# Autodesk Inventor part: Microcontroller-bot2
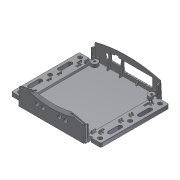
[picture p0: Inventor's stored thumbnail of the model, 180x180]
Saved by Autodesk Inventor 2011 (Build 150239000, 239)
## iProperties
Created: 2010-06
Part Number: Microcontroller-bot2
Document SubType Name: Modeling
Designer: kurdi
Density: 1 g/cm^3
Author: kurdi
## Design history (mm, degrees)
sketch "Sketch2"
  geometry: L1 (47.625, 12.7)-(47.625, 25.4); L2 (48.625, 12.7)-(48.625, 25.4); L3 (52.975, 25.4)-(52.975, 12.7); L4 (55.15, 1.25)-(55.15, 41.5); L5 (46.825, 42)-(54.65, 42); L6 (46.325, 40.5)-(46.325, 41.5); L7 (41.65, 40)-(45.825, 40); L8 (41.15, 34)-(41.15, 39.5); L9 (46.15, 24)-(46.15, 33); L10 (41.65, 33.5)-(45.65, 33.5); L11 (45.65, 23.5)-(41.65, 23.5); L12 (41.15, 0.5)-(41.15, 23); L13 (47.665, 0.5)-(41.15, 0.5); L14 (54.65, 0.75)-(54.256, 0.75); L15 (55.145, 43.511)-(44.825, 43.511); L16 (0, 0)-(91.681, 0) reference; L17 (0, 0)-(0, 55.36) reference; L18 (44.825, 43.511)-(44.825, 41.717); L19 (53.975, 25.4)-(53.975, 12.7); L20 (44.825, 41.717)-(42.375, 41.717); L21 (42.375, 41.717)-(42.375, 43.773); L22 (42.375, 43.773)-(42.7, 43.773); L23 (42.7, 43.773)-(42.7, 45.36); L24 (42.375, 45.36)-(42.7, 45.36); L25 (42.375, 45.36)-(42.375, 48.457); L26 (42.375, 48.457)-(41.363, 48.457); L27 (41.363, 48.457)-(41.363, 49.282); L28 (-41.15, 34)-(-41.15, 39.5); L29 (-46.325, 40.5)-(-46.325, 41.5); L30 (-46.825, 42)-(-54.65, 42); L31 (-46.15, 24)-(-46.15, 33); L32 (-47.625, 12.7)-(-47.625, 25.4); L33 (-48.625, 12.7)-(-48.625, 25.4); L34 (-45.65, 23.5)-(-41.65, 23.5); L35 (-55.15, 1.25)-(-55.15, 41.5); L36 (-52.975, 25.4)-(-52.975, 12.7); L37 (-41.15, 0.5)-(-41.15, 23); L38 (-41.65, 33.5)-(-45.65, 33.5); L39 (-41.65, 40)-(-45.825, 40); L40 (-55.145, 43.511)-(-44.825, 43.511); L41 (-47.665, 0.5)-(-41.15, 0.5); L42 (-54.65, 0.75)-(-54.256, 0.75); L43 (-44.825, 41.717)-(-42.375, 41.717); L44 (-44.825, 43.511)-(-44.825, 41.717); L45 (-42.375, 41.717)-(-42.375, 43.773); L46 (-42.375, 43.773)-(-42.7, 43.773); L47 (-42.7, 43.773)-(-42.7, 45.36); L48 (-42.375, 45.36)-(-42.375, 48.457); L49 (-42.375, 48.457)-(-41.363, 48.457); L50 (-41.363, 48.457)-(-41.363, 49.282); L51 (-42.375, 45.36)-(-42.7, 45.36); L52 (-53.975, 25.4)-(-53.975, 12.7); L53 (55.15, -1.25)-(55.15, -41.5); L54 (41.15, -0.5)-(41.15, -23); L55 (41.15, -34)-(41.15, -39.5); L56 (41.65, -40)-(45.825, -40); L57 (46.325, -40.5)-(46.325, -41.5); L58 (0, 0)-(0, -55.36); L59 (41.363, -48.457)-(41.363, -49.282); L60 (42.375, -48.457)-(41.363, -48.457); L61 (42.375, -41.717)-(42.375, -43.773); L62 (42.375, -45.36)-(42.7, -45.36); L63 (42.7, -43.773)-(42.7, -45.36); L64 (42.375, -43.773)-(42.7, -43.773)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; C1 r 2.175 at (50.8, 0); C2 r 2.75 at (36.195, 41.91); C3 r 1.4 at (36.195, 41.91); C4 r 3.25 at (50.8, 38.1); C5 r 2.175 at (50.8, 38.1); C6 r 2.175 at (-50.8, 38.1); C7 r 3.25 at (-50.8, 38.1); C8 r 2.175 at (-50.8, 0); C9 r 2.75 at (-36.195, 41.91); C10 r 1.4 at (-36.195, 41.91); C11 r 2.75 at (36.195, -41.91); C12 r 1.4 at (36.195, -41.91); C13 r 1.4 at (-36.195, -41.91); C14 r 2.75 at (-36.195, -41.91); C15 r 2.175 at (-50.8, -38.1); C16 r 3.25 at (-50.8, -38.1); C17 r 3.25 at (50.8, -38.1); C18 r 2.175 at (50.8, -38.1); A1 r 2.95 centre (50.8, 38.1) between (53.193, 39.825) and (48.592, 40.057); A2 r 2.175 centre (50.8, 25.4) between (52.975, 25.4) and (48.625, 25.4); A3 r 2.175 centre (50.8, 12.7) between (48.625, 12.7) and (52.975, 12.7); A4 r 0.5 centre (54.65, 41.5) between (55.15, 41.5) and (54.65, 42); A5 r 0.5 centre (46.825, 41.5) between (46.825, 42) and (46.325, 41.5); A6 r 0.5 centre (45.825, 40.5) between (45.825, 40) and (46.325, 40.5); A7 r 0.5 centre (41.65, 39.5) between (41.65, 40) and (41.15, 39.5); A8 r 0.5 centre (41.65, 34) between (41.15, 34) and (41.65, 33.5); A9 r 0.5 centre (45.65, 33) between (46.15, 33) and (45.65, 33.5); A10 r 0.5 centre (45.65, 24) between (45.65, 23.5) and (46.15, 24); A11 r 0.5 centre (41.65, 23) between (41.65, 23.5) and (41.15, 23); A12 r 3.175 centre (50.8, 0) between (53.786, 1.08) and (47.665, 0.5); A13 r 0.5 centre (54.256, 1.25) between (53.786, 1.08) and (54.256, 0.75); A14 r 0.5 centre (54.65, 1.25) between (54.65, 0.75) and (55.15, 1.25); A15 r 3.175 centre (50.8, 12.7) between (47.625, 12.7) and (53.975, 12.7); A16 r 3.175 centre (50.8, 25.4) between (53.975, 25.4) and (47.625, 25.4); A17 r 0.5 centre (-45.825, 40.5) between (-46.325, 40.5) and (-45.825, 40); A18 r 0.5 centre (-46.825, 41.5) between (-46.325, 41.5) and (-46.825, 42); A19 r 2.95 centre (-50.8, 38.1) between (-48.592, 40.057) and (-53.193, 39.825); A20 r 0.5 centre (-54.65, 41.5) between (-54.65, 42) and (-55.15, 41.5); A21 r 2.175 centre (-50.8, 25.4) between (-48.625, 25.4) and (-52.975, 25.4); A22 r 0.5 centre (-45.65, 33) between (-45.65, 33.5) and (-46.15, 33); A23 r 2.175 centre (-50.8, 12.7) between (-52.975, 12.7) and (-48.625, 12.7); A24 r 0.5 centre (-45.65, 24) between (-46.15, 24) and (-45.65, 23.5); A25 r 0.5 centre (-41.65, 23) between (-41.15, 23) and (-41.65, 23.5); A26 r 3.175 centre (-50.8, 0) between (-47.665, 0.5) and (-53.786, 1.08); A27 r 0.5 centre (-41.65, 34) between (-41.65, 33.5) and (-41.15, 34); A28 r 0.5 centre (-41.65, 39.5) between (-41.15, 39.5) and (-41.65, 40); A29 r 0.5 centre (-54.256, 1.25) between (-54.256, 0.75) and (-53.786, 1.08); A30 r 0.5 centre (-54.65, 1.25) between (-55.15, 1.25) and (-54.65, 0.75); A31 r 3.175 centre (-50.8, 25.4) between (-47.625, 25.4) and (-53.975, 25.4); A32 r 3.175 centre (-50.8, 12.7) between (-53.975, 12.7) and (-47.625, 12.7); A33 r 0.5 centre (45.825, -40.5) between (46.325, -40.5) and (45.825, -40); A34 r 0.5 centre (41.65, -39.5) between (41.15, -39.5) and (41.65, -40); A35 r 0.5 centre (41.65, -34) between (41.65, -33.5) and (41.15, -34); A36 r 0.5 centre (41.65, -23) between (41.15, -23) and (41.65, -23.5); A37 r 0.5 centre (45.65, -24) between (46.15, -24) and (45.65, -23.5); A38 r 0.5 centre (45.65, -33) between (45.65, -33.5) and (46.15, -33); A39 r 0.5 centre (54.256, -1.25) between (54.256, -0.75) and (53.786, -1.08); A40 r 3.175 centre (50.8, 0) between (47.665, -0.5) and (53.786, -1.08); A41 r 0.5 centre (54.65, -1.25) between (55.15, -1.25) and (54.65, -0.75); A42 r 0.5 centre (54.65, -41.5) between (54.65, -42) and (55.15, -41.5); A43 r 0.5 centre (46.825, -41.5) between (46.325, -41.5) and (46.825, -42); A44 r 0.5 centre (-45.825, -40.5) between (-45.825, -40) and (-46.325, -40.5); A45 r 2.95 centre (-50.8, -38.1) between (-53.193, -39.825) and (-48.592, -40.057); A46 r 0.5 centre (-45.65, -33) between (-46.15, -33) and (-45.65, -33.5); A47 r 0.5 centre (-41.65, -34) between (-41.15, -34) and (-41.65, -33.5); A48 r 3.175 centre (-50.8, -25.4) between (-53.975, -25.4) and (-47.625, -25.4); A49 r 2.175 centre (-50.8, -25.4) between (-52.975, -25.4) and (-48.625, -25.4); A50 r 0.5 centre (-45.65, -24) between (-45.65, -23.5) and (-46.15, -24); A51 r 0.5 centre (-41.65, -23) between (-41.65, -23.5) and (-41.15, -23); A52 r 2.175 centre (-50.8, -12.7) between (-48.625, -12.7) and (-52.975, -12.7); A53 r 3.175 centre (-50.8, 0) between (-53.786, -1.08) and (-47.665, -0.5); A54 r 0.5 centre (-54.65, -1.25) between (-54.65, -0.75) and (-55.15, -1.25); A55 r 3.175 centre (-50.8, -12.7) between (-47.625, -12.7) and (-53.975, -12.7); A56 r 0.5 centre (-46.825, -41.5) between (-46.825, -42) and (-46.325, -41.5); A57 r 0.5 centre (-54.65, -41.5) between (-55.15, -41.5) and (-54.65, -42); A58 r 0.5 centre (-41.65, -39.5) between (-41.65, -40) and (-41.15, -39.5); A59 r 0.5 centre (-54.256, -1.25) between (-53.786, -1.08) and (-54.256, -0.75); A60 r 2.175 centre (50.8, -12.7) between (52.975, -12.7) and (48.625, -12.7); A61 r 3.175 centre (50.8, -12.7) between (53.975, -12.7) and (47.625, -12.7); A62 r 3.175 centre (50.8, -25.4) between (47.625, -25.4) and (53.975, -25.4); A63 r 2.175 centre (50.8, -25.4) between (48.625, -25.4) and (52.975, -25.4); 17 further points
  constraints: 234 end point, 194 symmetric about line, 126 point on circle, 81 centre point, 20 perpendicular, 8 coincident, 4 tangent, 3 point on line, 2 collinear, 1 parallel, 91 other
  dimensions: "d9" = 99.16393 distance between parallel lines of L100 L102; "d10" = 114.28925 distance between parallel lines of L103 L101
extrude "Extrusion1" new body sketch "Sketch2" distance "d2" = 5.0038; taper "d3" = -1 deg
feature "FaceDraft6" dims angle "d95" = 1 deg
extrude "Extrusion2" cut sketch "Sketch2" distance "d4" = 2.9972; taper "d5" = 0 deg
fillet "Fillet1" dims "d6" = 0.3048
fillet "Fillet2" dims "d7" = 0.3048
fillet "Fillet3" dims "d8" = 0.3048
sketch "Sketch3"
  geometry: L1 (-48.238, 12.7)-(-48.238, 25.4) reference; L2 (-39.141, -39.073)-(-39.141, 39.073); L3 (-40.183, -47.498)-(40.183, -47.498); L4 (40.183, 47.498)-(-40.183, 47.498); L5 (-40.183, 47.498)-(-40.183, 43.356); L6 (-40.183, -43.356)-(-40.183, -47.498); L7 (39.141, -38.859)-(39.141, 38.858); L8 (40.183, -47.498)-(40.183, -43.356); L9 (40.183, 43.356)-(40.183, 47.498); C1 r 2.837 at (-36.195, -41.91) reference; C2 r 2.837 at (36.195, -41.91) reference; C3 r 2.837 at (-36.195, 41.91) reference; C4 r 2.837 at (36.195, 41.91) reference; A1 r 4.242 centre (-36.195, -41.91) between (-40.183, -43.356) and (-39.141, -38.858); A2 r 4.242 centre (-36.195, 41.91) between (-39.141, 38.858) and (-40.183, 43.356); A3 r 4.242 centre (36.195, -41.91) between (39.141, -38.859) and (40.183, -43.356); A4 r 4.242 centre (36.195, 41.91) between (40.183, 43.356) and (39.141, 38.858); 1 further point
  constraints: 16 end point, 8 point on circle, 7 parallel, 4 centre point, 4 coincident, 3 equal radius, 2 collinear, 2 perpendicular, 2 point on line, 1 horizontal
  dimensions: "d11" = 47.498 distance from line of L3 point (0, 0); "d12" = 47.498 distance from line of L4 point (0, 0); "d13" = 8.4836 diameter of A1; "d15" = 39.1414 distance from line of L2 point (0, 0); "d16" = 40.1828 distance from line of point (0, 0) L6; "d17" = 39.1414 distance from line of point (0, 0) L7; "d18" = 40.1828 distance from line of L8 point (0, 0)
extrude "Extrusion3" cut sketch "Sketch3" distance "d19" = 2.9972; taper "d20" = 0 deg
sketch "Sketch4"
  geometry: L1 (-40.208, 38.989)-(-41.504, 38.989); L2 (-41.504, 38.989)-(-41.504, 33.985); L3 (-41.504, 33.985)-(-40.208, 33.985); L4 (-40.208, 33.985)-(-40.208, 38.989); L5 (-44.171, 25.502)-(-41.859, 25.502); L6 (-41.859, 25.502)-(-41.859, 31.496); L7 (-41.859, 31.496)-(-44.171, 31.496); L8 (-44.171, 31.496)-(-44.171, 25.502); L9 (-44.45, 34.011)-(-47.447, 34.011); L10 (-47.447, 34.011)-(-47.447, 33.02); L11 (-47.447, 33.02)-(-44.45, 33.02); L12 (-44.45, 33.02)-(-44.45, 34.011); L13 (-44.45, 31.013)-(-47.447, 31.013); L14 (-47.447, 31.013)-(-47.447, 30.023); L15 (-47.447, 30.023)-(-44.45, 30.023); L16 (-44.45, 30.023)-(-44.45, 31.013); C1 r 2.837 at (-36.195, 41.91) reference; A1 r 4.242 centre (-36.195, 41.91) between (-39.141, 38.858) and (-40.183, 43.356) reference; 1 further point
  constraints: 32 end point, 8 parallel, 4 horizontal, 4 perpendicular, 3 collinear
  dimensions: "d21" = 1.2954 distance of L1.start L1.end; "d22" = 5.0038 distance of L1.end L2.end; "d23" = 4.0132 distance from line of A1.centre L4; "d24" = 2.921 distance from line of A1.centre L1; "d25" = 5.6642 distance from line of A1.centre L6; "d26" = 10.414 distance from line of C1.centre L7; "d27" = 5.9944 distance of L7.end L5.start; "d28" = 2.3114 distance of L5.start L5.end; "d29" = 0.9906 distance of L9.end L10.end; "d30" = 2.9972 distance of L9.start L9.end; "d31" = 8.255 distance from line of A1.centre L12; "d32" = 7.8994 distance from line of C1.centre L9; "d33" = 2.0066 distance between parallel lines of L13 L11
extrude "Extrusion4" join sketch "Sketch4" distance "d34" = 3.6068; taper "d35" = -2 deg
extrude "Extrusion5" cut sketch "Sketch4" distance "d36" = 3.5052; taper "d37" = 0 deg
extrude "Extrusion6" join sketch "Sketch4" distance "d38" = 2.4892; taper "d39" = 0 deg
chamfer "Chamfer1" distance "d40" = 2.4892; stored, may be unused: second distance "d41" = 3.175, angle "d42" = 45 deg
workplane "Work Plane1"
mirror "Mirror1"
mirror "Mirror2"
mirror "Mirror3"
mirror "Mirror4"
sketch "Sketch5"
  geometry: L1 (-40.183, 43.356)-(-40.183, 47.498) reference; L2 (-39.141, 38.858)-(-39.141, 44.962); L3 (-39.141, -38.858)-(-39.141, 38.858) reference; L4 (39.141, 38.858)-(39.141, -38.859) reference; L5 (-48.238, 12.7)-(-48.238, 25.4) reference; L6 (-39.141, -38.858)-(-39.141, -44.961); L7 (39.141, -38.859)-(39.141, -44.962); L8 (39.141, 38.858)-(39.141, 44.961); C1 r 2.837 at (-36.195, 41.91) reference; C2 r 1.397 at (-36.195, 41.91); C3 r 2.837 at (-36.195, -41.91) reference; C4 r 2.837 at (36.195, 41.91) reference; C5 r 1.397 at (-36.195, -41.91); C6 r 1.397 at (36.195, -41.91); C7 r 1.397 at (36.195, 41.91); A1 r 4.242 centre (-36.195, 41.91) between (-39.141, 38.858) and (-40.183, 43.356) reference; A2 r 4.242 centre (-36.195, 41.91) between (-39.141, 38.858) and (-39.141, 44.962); A3 r 4.242 centre (-36.195, -41.91) between (-40.183, -43.356) and (-39.141, -38.858) reference; A4 r 4.242 centre (36.195, 41.91) between (40.183, 43.356) and (39.141, 38.858) reference; A5 r 4.242 centre (36.195, -41.91) between (39.141, -38.859) and (40.183, -43.356) reference; A6 r 4.242 centre (-36.195, -41.91) between (-39.141, -44.961) and (-39.141, -38.858); A7 r 4.242 centre (36.195, -41.91) between (39.141, -38.859) and (39.141, -44.962); A8 r 4.242 centre (36.195, 41.91) between (39.141, 44.961) and (39.141, 38.858); 1 further point
  constraints: 12 point on circle, 8 centre point, 8 end point, 7 coincident, 4 equal radius, 3 collinear, 2 parallel, 1 concentric
  dimensions: "d44" = 2.794 diameter of C2
extrude "Extrusion7" join sketch "Sketch5" distance "d45" = 0.9906; taper "d46" = 0 deg
sketch "Sketch6"
  geometry: C1 r 1.397 at (0, 0) reference; C2 r 2.837 at (0, 0) reference; C3 r 1.397 at (0, 83.82) reference; C4 r 2.837 at (0, 83.82) reference; C5 r 1.397 at (72.39, 0) reference; C6 r 2.837 at (72.39, 0) reference; C7 r 1.397 at (72.39, 83.82) reference; C8 r 2.837 at (72.39, 83.82) reference; 1 further point
extrude "Extrusion8" join sketch "Sketch6" distance "d47" = 1.2192; taper "d48" = 0 deg
feature "FaceDraft1" dims angle "d49" = 1 deg
feature "FaceDraft2" dims angle "d50" = -1 deg
sketch "Sketch7"
  geometry: L1 (82.814, 0)-(0, 0) reference; L2 (82.814, 0)-(-0.001, 0); L3 (41.363, 0.865)-(41.422, 25.357); L4 (82.814, 0)-(82.183, 19.389); L5 (-0.001, 0)-(0.711, 19.069); C1 r 1.6 at (23.363, 13.636); C2 r 1.6 at (31.063, 13.636); C3 r 1.6 at (51.663, 13.636); C4 r 1.6 at (59.363, 13.636); A1 r 156.845 centre (42.062, -131.487) between (81.422, 20.339) and (1.463, 20.013); A2 r 1.016 centre (1.726, 19.031) between (1.463, 20.013) and (0.711, 19.069); A3 r 1.016 centre (81.167, 19.356) between (82.183, 19.389) and (81.422, 20.339); 2 further points
  constraints: 8 end point, 8 point on circle, 7 centre point, 4 tangent, 3 horizontal alignment, 2 collinear, 1 equal radius
  dimensions: "d53" = 156.845 radius of A1; "d55" = 132.35208 vertical distance of L3.start A1.centre; "d56" = 1.016 radius of A2; "d58" = 18.00015 horizontal distance of L3.start C1.centre; "d59" = 17.99985 horizontal distance of L3.start C4.centre; "d60" = 10.29985 horizontal distance of L3.start C3.centre; "d61" = 10.30015 horizontal distance of L3.start C2.centre; "d62" = 12.77056 vertical distance of L3.start C1.centre; "d63" = 3.2004 diameter of C1; "d64" = 3.2004 diameter of C2; "d65" = 3.2004 diameter of C3; "d66" = 3.2004 diameter of C4; "d96" = 2 deg angle of L3 L4; "d97" = 2 deg angle of L3 L5
extrude "Extrusion9" join sketch "Sketch7" stored distance "d75" = 1.2192; taper "d76" = 0 deg
sketch "Sketch8"
  geometry: L1 (0, 0)-(0.262, 5.005) reference; L2 (84.837, 0)-(84.662, 5.005) reference; L3 (-0.001, -0.02)-(1.128, 21.534); L4 (84.838, -0.02)-(84.101, 21.072); L5 (-0.001, -0.02)-(84.838, -0.02); L6 (42.419, -0.02)-(42.419, 26.836); A1 r 156.845 centre (41.763, -131.506) between (82.362, 19.993) and (2.403, 20.32) reference; A2 r 158.344 centre (41.763, -131.506) between (84.101, 21.072) and (1.128, 21.534); 8 further points; 2 other entities
  constraints: 8 end point, 4 collinear, 3 point on circle, 2 horizontal, 1 centre point, 1 concentric, 1 vertical, 3 other
  dimensions: "d77" = 1.4986 radial gap between concentric circles of A1 A2
extrude "Extrusion10" join sketch "Sketch8" stored distance "d79" = 0.889; taper "d80" = 0 deg
sketch "Sketch9"
  geometry: C1 r 1.6 at (0, 0) reference; C2 r 1.6 at (7.7, 0) reference; C3 r 1.6 at (28.3, 0) reference; C4 r 1.6 at (36, 0) reference; 1 further point
  node "Projected Loop4"
  node "Projected Loop5"
  node "Projected Loop6"
extrude "Extrusion19" cut sketch "Sketch9" stored distance "d133" = 12.7; taper "d134" = 0 deg
fillet "Fillet4" dims "d85" = 1.016
chamfer "Chamfer2" distance "d86" = 0.762; stored, may be unused: second distance "d87" = 3.175, angle "d88" = 45 deg
sketch "Sketch10"
  geometry: L1 (42.613, -45.273)-(42.2, -45.273) reference; L2 (42.613, -43.86)-(42.613, -45.273) reference; L3 (42.287, -43.86)-(42.613, -43.86) reference; L4 (40.183, -43.406)-(40.183, -47.498) reference; L5 (44.171, -31.496)-(41.859, -31.496) reference; L6 (41.413, -47.559)-(41.413, -45.273); L7 (41.413, -43.86)-(41.413, -42.87); L8 (41.413, -42.87)-(40.183, -42.87); L9 (40.183, -42.87)-(40.183, -43.406); L10 (41.413, -45.273)-(42.2, -45.273); L11 (41.413, -43.86)-(42.287, -43.86); L12 (41.413, -47.559)-(40.183, -47.559); L13 (40.183, -47.559)-(40.183, -47.498); L14 (41.413, -43.86)-(40.183, -43.86); L15 (40.183, -43.86)-(40.183, -43.406); L16 (40.183, -43.86)-(40.183, -47.498); L17 (-41.177, -49.495)-(-41.176, -48.37) reference; L18 (41.413, -43.86)-(41.412, -44.114); L19 (41.412, -44.114)-(40.183, -44.114); 1 further point
  constraints: 26 end point, 5 perpendicular, 4 collinear, 3 parallel, 2 point on line, 1 horizontal, 1 vertical
  dimensions: "d89" = 0.7874 distance of L6.end L1.end; "d90" = 2.286 distance between parallel lines of L10 L12; "d91" = 0.9906 distance between parallel lines of L11 L8; "d262" = 0.254 distance of L7.start L18.end
extrude "Extrusion12" join sketch "Sketch10" distance "d92" = 12.8524; taper "d93" = 0 deg
feature "FaceDraft7" dims angle "d98" = 1 deg
chamfer "Chamfer9" distance "d247" = 12.7; stored, may be unused: second distance "d248" = 0.2032, angle "d249" = 45 deg
chamfer "Chamfer10" distance "d250" = 12.7; stored, may be unused: second distance "d251" = 0.2032, angle "d252" = 45 deg
feature "FaceDraft15" dims angle "d272" = 2 deg
sketch "Sketch13"
  geometry: L1 (40.183, -44.288)-(42.164, -44.288) reference; L2 (40.183, -47.498)-(40.183, -44.288) reference; L3 (41.413, -47.498)-(40.183, -47.498) reference; L4 (41.413, -45.07)-(41.413, -47.498) reference; L5 (42.164, -45.07)-(41.413, -45.07) reference; L6 (42.164, -44.288)-(42.164, -45.07) reference; 1 further point
extrude "Extrusion13" join sketch "Sketch13" distance "d101" = 1.524; taper "d102" = 0 deg
fillet "Fillet5" dims "d103" = 1.016
extrude "Extrusion17" join sketch "Sketch10" distance "d125" = 5.9944; taper "d126" = 0 deg
chamfer "Chamfer3" distance "d127" = 5.0038; stored, may be unused: second distance "d128" = 0.508, angle "d129" = 45 deg
mirror "Mirror5"
feature "FaceDraft9" dims angle "d100" = 2 deg
sketch "Sketch23"
  geometry: L1 (-1.981, 3.434)-(-1.981, 2.428) reference; L2 (-0.781, 2.428)-(-1.981, 2.428) reference; L3 (-0.781, 0)-(-0.781, 2.428) reference; L4 (0, 0)-(-0.781, 0) reference; L5 (0, 0)-(0, 3.434) reference; L6 (-1.981, 3.434)-(0, 3.434) reference; 1 further point
extrude "Extrusion27" join sketch "Sketch23" distance "d259" = 1.524; taper "d260" = 0 deg
fillet "Fillet6" dims "d261" = 1.016
sketch "Sketch14"
  geometry: L1 (82.816, 0.099)-(0.002, -0.099); L2 (82.816, 0.099)-(0.001, -0.099); L3 (41.363, 0.867)-(41.363, 25.357); L4 (82.816, 0.099)-(82.139, 19.486); L5 (0.001, -0.099)-(0.667, 18.972); L6 (48.817, 10.871)-(62.341, 10.871); L7 (47.928, 19.083)-(47.928, 11.76); L8 (52.378, 19.972)-(48.817, 19.972); L9 (52.378, 21.672)-(52.378, 19.972); L10 (58.782, 21.672)-(52.378, 21.672); L11 (58.782, 19.972)-(58.782, 21.672); L12 (62.341, 19.972)-(58.782, 19.972); L13 (63.23, 11.76)-(63.23, 19.083); L14 (64.968, 15.186)-(64.968, 12.685); L15 (70.268, 12.685)-(70.268, 15.186); L16 (30.867, 6.782)-(30.867, 6.97); L17 (27.818, 6.782)-(30.867, 6.782); L18 (27.818, 6.782)-(27.818, 6.97); L19 (18.667, 6.97)-(27.818, 6.97); L20 (18.667, 6.782)-(18.667, 6.97); L21 (14.618, 6.782)-(18.667, 6.782); L22 (14.618, 6.782)-(14.618, 6.97); L23 (10.208, 6.97)-(14.618, 6.97); L24 (9.318, 19.083)-(9.319, 7.859); L25 (46.429, 19.972)-(10.207, 19.972); L26 (47.319, 7.859)-(47.318, 19.083); L27 (42.567, 6.97)-(46.43, 6.97); L28 (42.567, 6.782)-(42.567, 6.97); L29 (39.518, 6.782)-(42.567, 6.782); L30 (39.518, 6.782)-(39.518, 6.97); L31 (30.867, 6.97)-(39.518, 6.97); L32 (65.349, 15.184)-(65.349, 12.684); L33 (69.887, 12.674)-(69.887, 15.184); L34 (46.937, 19.083)-(46.938, 7.859); L35 (46.429, 7.351)-(42.567, 7.351); L36 (39.518, 7.351)-(30.867, 7.351); L37 (27.818, 7.351)-(18.667, 7.351); L38 (14.618, 7.351)-(10.207, 7.351); L39 (9.7, 7.859)-(9.699, 19.083); L40 (10.207, 19.591)-(46.429, 19.591); L41 (62.849, 19.083)-(62.849, 11.76); L42 (62.341, 11.252)-(48.817, 11.252); L43 (48.309, 11.76)-(48.309, 19.083); L44 (48.817, 19.591)-(52.759, 19.591); L45 (52.759, 19.591)-(52.759, 21.291); L46 (52.759, 21.291)-(58.401, 21.291); L47 (58.401, 21.291)-(58.401, 19.591); L48 (58.401, 19.591)-(62.341, 19.591); L49 (42.567, 7.351)-(42.567, 6.782); L50 (42.567, 6.782)-(39.518, 6.782); L51 (39.518, 7.351)-(39.518, 6.782); L52 (30.867, 7.351)-(30.867, 6.782); L53 (30.867, 6.782)-(27.818, 6.782); L54 (27.818, 6.782)-(27.818, 7.351); L55 (14.618, 7.351)-(14.618, 6.782); L56 (14.618, 6.782)-(18.667, 6.782); L57 (18.667, 6.782)-(18.667, 7.351); L58 (1.18, 2.043)-(81.546, 2.043) reference; L59 (30.867, 7.351)-(26, 7.351); A1 r 156.845 centre (42.378, -131.485) between (81.376, 20.435) and (1.417, 19.917); A2 r 1.016 centre (1.683, 18.937) between (1.417, 19.917) and (0.667, 18.972); A3 r 1.016 centre (81.123, 19.451) between (82.139, 19.486) and (81.376, 20.435); A4 r 0.889 centre (48.817, 19.083) between (48.817, 19.972) and (47.928, 19.083); A5 r 0.889 centre (62.341, 19.083) between (63.23, 19.083) and (62.341, 19.972); A6 r 0.889 centre (48.817, 11.76) between (47.928, 11.76) and (48.817, 10.871); A7 r 0.889 centre (62.341, 11.76) between (62.341, 10.871) and (63.23, 11.76); A8 r 0.889 centre (46.43, 7.859) between (46.43, 6.97) and (47.319, 7.859); A9 r 0.889 centre (46.429, 19.083) between (47.318, 19.083) and (46.429, 19.972); A10 r 0.889 centre (10.207, 19.083) between (10.207, 19.972) and (9.318, 19.083); A11 r 0.889 centre (10.208, 7.859) between (9.319, 7.859) and (10.208, 6.97); A12 r 0.508 centre (46.43, 7.859) between (46.429, 7.351) and (46.938, 7.859); A13 r 0.508 centre (10.208, 7.859) between (9.7, 7.859) and (10.207, 7.351); A14 r 0.508 centre (10.207, 19.083) between (10.207, 19.591) and (9.699, 19.083); A15 r 0.508 centre (46.429, 19.083) between (46.937, 19.083) and (46.429, 19.591); A16 r 0.508 centre (62.341, 11.76) between (62.341, 11.252) and (62.849, 11.76); A17 r 0.508 centre (48.817, 11.76) between (48.309, 11.76) and (48.817, 11.252); A18 r 0.508 centre (48.817, 19.083) between (48.817, 19.591) and (48.309, 19.083); A19 r 0.508 centre (62.341, 19.083) between (62.849, 19.083) and (62.341, 19.591); 2 further points
  constraints: 116 end point, 40 point on circle, 20 tangent, 19 centre point, 8 point on line, 7 perpendicular, 6 collinear, 6 parallel, 5 vertical, 4 horizontal, 2 horizontal alignment, 1 equal radius, 26 other
  dimensions: "d104" = 156.845 radius of A1; "d105" = 132.35208 vertical distance of L3.start A1.centre; "d106" = 1.016 radius of A2; "d116" = 2 deg angle of L3 L4; "d117" = 2 deg angle of L3 L5; "d140" = 0.381 distance between parallel lines of L14 L32; "d141" = 0.889 radius of A4; "d142" = 0.889 radius of A5; "d143" = 0.889 radius of A6; "d144" = 0.889 radius of A7; "d145" = 0.889 radius of A8; "d146" = 0.889 radius of A9; "d147" = 0.889 radius of A10; "d148" = 0.889 radius of A11; "d149" = 0.381 distance between parallel lines of L26 L34; "d150" = 0.381 distance between parallel lines of L41 L13; "d168" = 5.3086 distance between parallel lines of L58 L59; "d169" = 0.61 distance between parallel lines of L7 L26; "d170" = 3.561 distance of L8.start L8.end; "d171" = 5.64198 distance of L45.end L46.end; "d172" = 3.94001 distance of L47.end L48.end; "d173" = 3.942 distance of L44.start L44.end; "d174" = 36.222 distance of L40.start L40.end; "d175" = 37.238 distance between parallel lines of L34 L39; "d176" = 9.15069 distance of L37.start L37.end; "d177" = 8.65069 distance of L36.start L36.end; "d178" = 4.411 distance of L38.start L38.end; "d179" = 3.86169 distance of L35.start L35.end; "d181" = 12.23986 distance between parallel lines of L37 L40; "d182" = 0.381 distance between parallel lines of L19 L37; "d183" = 0.381 distance between parallel lines of L23 L38; "d184" = 0.381 distance between parallel lines of L31 L36; "d185" = 0.381 distance between parallel lines of L27 L35; "d186" = 0.381 distance between parallel lines of L25 L40; "d187" = 3.90059 distance between parallel lines of L6 L27; "d188" = 2.50077 distance of L15.start L15.end; "d189" = 5.3 distance between parallel lines of L14 L15; "d190" = 8.33926 distance between parallel lines of L42 L48; "d191" = 0.56878 distance between parallel lines of L37 L21; "d192" = 0.56878 distance between parallel lines of L17 L37; "d193" = 0.56878 distance between parallel lines of L29 L36; "d194" = 3.04931 distance of L29.start L28.start; "d195" = 3.04931 distance of L17.start L16.start; "d196" = 5.3086 distance from line of L58 L36.end; "d197" = 4.31485 distance from line of L6 L14.start; "d287" = 1.73801 distance from line of L13 L14.start; "d289" = 6.94617 distance from line of L3 L43.start
extrude "Extrusion14" join sketch "Sketch14" stored distance "d118" = 1.524; taper "d119" = 0 deg
sketch "Sketch15"
  geometry: L1 (-1.175, -5.005)-(-0.913, 0); L2 (83.662, -5.005)-(83.487, 0); L3 (-1.176, -5.024)-(-0.047, 16.53); L4 (83.663, -5.024)-(82.926, 16.068); L5 (-1.176, -5.024)-(83.663, -5.024); L6 (-0.163, -5.024)-(82.651, -5.024); L7 (41.244, -5.024)-(41.244, 21.831); A1 r 156.845 centre (40.588, -136.511) between (81.187, 14.988) and (1.228, 15.315); A2 r 158.344 centre (40.588, -136.511) between (82.926, 16.068) and (-0.047, 16.53); 7 further points; 1 other entity
  constraints: 14 end point, 5 collinear, 5 point on circle, 2 centre point, 1 concentric, 1 horizontal, 1 midpoint, 1 vertical, 3 other
  dimensions: "d120" = 1.4986 radial gap between concentric circles of A1 A2
extrude "Extrusion15" join sketch "Sketch15" stored distance "d121" = 0.889; taper "d122" = 0 deg
mirror "Mirror7"
extrude "Extrusion18" cut sketch "Sketch14" stored distance "d131" = 12.7; taper "d132" = 0 deg
sketch "Sketch16"
  geometry: L1 (4.088, -9.715)-(0.61, 9.539); L2 (0, -9.715)-(4.088, -9.715); L3 (86.261, -9.715)-(8.736, -9.715) reference; L4 (0, 7.324)-(0, 0) reference; L5 (0, 10.284)-(0, -9.715); A1 r 0.991 centre (-0.365, 9.363) between (0.61, 9.539) and (0, 10.284); 2 further points
  constraints: 6 end point, 3 collinear, 2 point on circle, 1 centre point, 1 tangent
  dimensions: "d232" = 0.9906 radius of A1; "d233" = 1.65715 distance from line of point (47.498, -11.372) L3; "d235" = 12.71867 distance from line of point (47.1, 3.004) L3; "d237" = 19.99912 distance of L5.start L2.start
extrude "Extrusion20" join sketch "Sketch16" distance "d135" = 0.9906; taper "d136" = 0 deg
sketch "Sketch28"
  geometry: L1 (-4.088, -9.715)-(-0.61, 9.539) reference; L2 (0, -9.715)-(-4.088, -9.715) reference; L3 (0, 10.284)-(0, -9.715) reference; 2 further points; 1 other entity
  constraints: 1 other
extrude "Extrusion31" join sketch "Sketch28" distance "d290" = 0.9906; taper "d291" = 0 deg
chamfer "Chamfer4" distance "d153" = 0.381; stored, may be unused: second distance "d154" = 0.508, angle "d155" = 45 deg
chamfer "Chamfer5" distance "d156" = 0.381; stored, may be unused: second distance "d157" = 0.508, angle "d158" = 45 deg
chamfer "Chamfer6" distance "d159" = 0.381; stored, may be unused: second distance "d160" = 0.508, angle "d161" = 45 deg
workplane "Work Plane2"
sketch "Sketch18"
  geometry: L1 (0, 10.284)-(0, -9.715) reference; L2 (-2.108, -9.719)-(-2.108, -9.414); L3 (-2.108, -9.414)-(-0.102, -4.409); L4 (-0.102, -4.409)-(0, -4.408); L5 (-86.261, -9.715)-(-8.736, -9.715) reference; L6 (0.305, -4.402)-(0.305, -9.677); L7 (0, -4.408)-(0.305, -4.402); L8 (0, -4.408)-(1.575, -4.38) reference; L9 (0.305, -9.677)-(-2.108, -9.719); 2 further points
  constraints: 12 end point, 2 collinear, 1 parallel, 1 point on line, 1 vertical
  dimensions: "d163" = 0.3048 distance of L2.start L2.end; "d164" = 0.1016 distance of L3.end L4.end
extrude "Extrusion22" join sketch "Sketch18" distance "d208" = 1.4986; taper "d209" = 0 deg
sketch "Sketch22"
  geometry: L1 (0, 0)-(0, 0.569) reference; L2 (1.34, 0)-(0, 0) reference; L3 (1.34, 0.569)-(1.34, 0) reference; L4 (1.34, 0.569)-(0, 0.569) reference; 1 further point
extrude "Extrusion26" cut sketch "Sketch22" distance "d226" = 0.635; taper "d227" = 0 deg
mirror "Mirror8"
workplane "Work Plane3"
sketch "Sketch20"
  geometry: L1 (2.108, 5.31)-(2.108, 0.035) reference; L2 (2.007, 5.308)-(2.108, 5.31) reference; L3 (0, 0.303)-(2.007, 5.308) reference; L4 (0, 0)-(0, 0.303) reference; L5 (0.092, 0)-(0, 0) reference; L6 (2.108, 0.035)-(0.092, 0) reference; 1 further point
extrude "Extrusion24" join sketch "Sketch20" distance "d213" = 1.4986; taper "d214" = 0 deg
sketch "Sketch21"
  geometry: L1 (40.183, 43.549)-(40.183, 47.498) reference; L2 (35.458, 48.006)-(36.957, 48.006); L3 (36.957, 48.006)-(36.957, 45.923); L4 (36.957, 45.923)-(35.458, 45.923); L5 (35.458, 45.923)-(35.458, 48.006); L6 (40.183, 47.498)-(-40.183, 47.498) reference; A1 r 4.311 centre (36.195, 41.91) between (40.183, 43.549) and (39.141, 38.762) reference; 2 further points
  constraints: 8 end point, 2 parallel, 1 horizontal, 1 perpendicular
  dimensions: "d216" = 1.4986 distance of L2.start L2.end; "d218" = 4.0132 distance from line of L4 A1.centre; "d238" = 3.2258 distance between parallel lines of L3 L1; "d239" = 0.508 distance between parallel lines of L6 L2
extrude "Extrusion25" join sketch "Sketch21" distance "d220" = 6.8072; taper "d221" = 0 deg
chamfer "Chamfer7" distance "d222" = 0.7112; stored, may be unused: second distance "d223" = 0.508, angle "d224" = 45 deg
mirror "Mirror9"
mirror "Mirror10"
fillet "Fillet9" dims "d269" = 1.016
feature "FaceDraft13" dims angle "d242" = 1 deg
fillet "Fillet11" dims "d271" = 1.016
sketch "Sketch26"
  geometry: L1 (16.393, 49.804)-(25.627, 46.259); L2 (5.004, 49.495)-(19.066, 49.249) reference; L3 (19.38, 47.498)-(2.007, 47.498) reference; L4 (5.004, 49.495)-(5.004, 49.495) reference; L5 (0.306, 49.577)-(5.004, 49.495) reference; L6 (0, 49.582)-(0.306, 49.577) reference; L7 (0, 49.582)-(0, 49.582) reference; L8 (19.386, 49.244)-(0, 49.582) reference; L9 (5.004, 49.495)-(19.066, 49.249) reference; L10 (16.393, 49.804)-(30.766, 49.553); L11 (30.766, 49.553)-(30.707, 46.171); L12 (30.707, 46.171)-(25.627, 46.259); L13 (0, 49.582)-(17.78, 49.272); L14 (17.78, 49.272)-(114.285, 47.587); L15 (114.285, 47.587)-(113.403, -2.948); 10 further points; 7 other entities
  constraints: 14 end point, 2 parallel, 2 perpendicular, 1 collinear, 1 midpoint, 1 point on line, 9 other
  dimensions: "d273" = 0.508 distance from line of point (-131.467, 51.877) L10; "d275" = 3.38285 distance of L10.end L11.end; "d276" = 20 deg angle of L1 L10; "d277" = 5.08 horizontal distance of L11.end L1.end; "d279" = 17.78 horizontal distance of L13.start L13.end; "d280" = 96.52 distance of L13.end L14.end
revolve "Revolution1" sketch "Sketch26" stored, may be unused: angle "d281" = 90 deg
fillet "Fillet14" dims "d284" = 1.524
sketch "Sketch27"
  geometry: L1 (62.71, 64.128)-(-63.473, 64.128); L2 (-63.473, 64.128)-(-63.473, -70.344); L3 (-63.473, -70.344)-(62.71, -70.344); L4 (62.71, -70.344)-(62.71, 64.128)
  constraints: 8 end point, 2 parallel, 1 horizontal, 1 perpendicular
extrude "Extrusion30" cut sketch "Sketch27" distance "d285" = 1.27; taper "d286" = 0 deg
body "Solid1"
node "Projected Loop1"
node "Projected Loop2"
node "Projected Loop3"
node "Projected Loop8"
node "Projected Loop9"
node "Projected Loop10"
node "Projected Loop11"
other parameters: "d14" = 40.1828, "d43" = 10.7442, "d162" = 18.161, "d212" = 17.78
